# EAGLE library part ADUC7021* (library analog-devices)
Precision Analog Microcontroller 12-bit Analog I/O, ARM7TDMI® MCU ADuC7021 Source: Source: http://www.analog.com/UploadedFiles/Data_Sheets/288945048AD7C7019_20_1_2_4_5_6_7_0.pdf
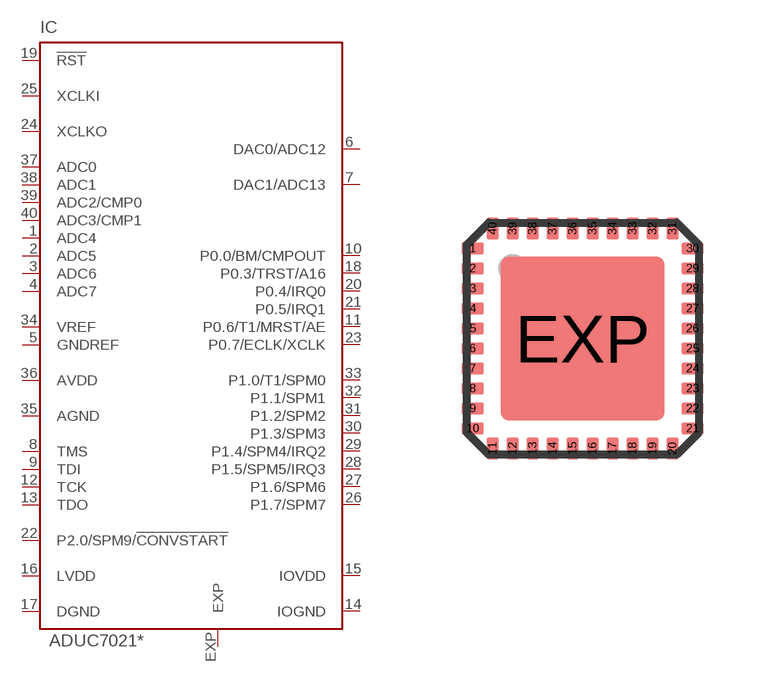
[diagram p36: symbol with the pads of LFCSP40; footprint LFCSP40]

Designator prefix IC

## ADUC7021BCPZ32 (MPN: ADUC7021BCPZ32; OC_FARNELL: 1274142; OC_NEWARK: 31M3910), ADUC7021BCPZ32-RL (OC_FARNELL: unknown; OC_NEWARK: unknown), ADUC7021BCPZ32-RL7 (OC_FARNELL: unknown; OC_NEWARK: unknown), ADUC7021BCPZ62 (MPN: ADUC7021BCPZ62; OC_FARNELL: 1162635; OC_NEWARK: 31M3911), ADUC7021BCPZ62-RL (OC_FARNELL: unknown; OC_NEWARK: unknown), ADUC7021BCPZ62-RL7 (OC_FARNELL: unknown; OC_NEWARK: unknown), ADUC7021BCPZ62I (MPN: ADUC7021BCPZ62I; OC_FARNELL: 1162636; OC_NEWARK: 19M0738), ADUC7021BCPZ62I-RL (OC_FARNELL: unknown; OC_NEWARK: unknown), ADUC7021BCPZ62IRL7 (OC_FARNELL: unknown; OC_NEWARK: unknown)  [LFCSP40]
1  ADC4  in
2  ADC5  in
3  ADC6  in
4  ADC7  in
5  GNDREF  in
6  DAC0/ADC12  in
7  DAC1/ADC13  in
8  TMS  in
9  TDI  in
10  P0.0/BM/CMPOUT
11  P0.6/T1/MRST/AE
12  TCK  in
13  TDO  out
14  IOGND  pwr
15  IOVDD  pwr
16  LVDD  out
17  DGND  pwr
18  P0.3/TRST/A16
19  !RST  in
20  P0.4/IRQ0
21  P0.5/IRQ1
22  P2.0/SPM9/!CONVSTART
23  P0.7/ECLK/XCLK
24  XCLKO  out
25  XCLKI  in
26  P1.7/SPM7
27  P1.6/SPM6
28  P1.5/SPM5/IRQ3
29  P1.4/SPM4/IRQ2
30  P1.3/SPM3
31  P1.2/SPM2
32  P1.1/SPM1
33  P1.0/T1/SPM0
34  VREF  pas
35  AGND  pwr
36  AVDD  pwr
37  ADC0  in
38  ADC1  in
39  ADC2/CMP0  in
40  ADC3/CMP1  in
EXP  EXP  pas

## Footprint LFCSP40 (pad centres in mm)
40-Lead Frame Chip Scale Package [LFCSP_VQ] 6 mm x 6 mm Body, Very Thin Quad (CP-40) COMPLIANT TO JEDEC STANDARDS MO-220-VJJD-2 Source: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
smd 0.55 x 0.3: 1 -2.75,2.25; 2 -2.75,1.75; 3 -2.75,1.25; 4 -2.75,0.75; 5 -2.75,0.25; 6 -2.75,-0.25; 7 -2.75,-0.75; 8 -2.75,-1.25; 9 -2.75,-1.75; 10 -2.75,-2.25; 21 2.75,-2.25; 22 2.75,-1.75; 23 2.75,-1.25; 24 2.75,-0.75; 25 2.75,-0.25; 26 2.75,0.25; 27 2.75,0.75; 28 2.75,1.25; 29 2.75,1.75; 30 2.75,2.25
smd 0.3 x 0.55: 11 -2.25,-2.75; 12 -1.75,-2.75; 13 -1.25,-2.75; 14 -0.75,-2.75; 15 -0.25,-2.75; 16 0.25,-2.75; 17 0.75,-2.75; 18 1.25,-2.75; 19 1.75,-2.75; 20 2.25,-2.75; 31 2.25,2.75; 32 1.75,2.75; 33 1.25,2.75; 34 0.75,2.75; 35 0.25,2.75; 36 -0.25,2.75; 37 -0.75,2.75; 38 -1.25,2.75; 39 -1.75,2.75; 40 -2.25,2.75
smd 4.1 x 4.1: EXP 0,0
